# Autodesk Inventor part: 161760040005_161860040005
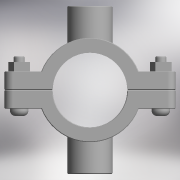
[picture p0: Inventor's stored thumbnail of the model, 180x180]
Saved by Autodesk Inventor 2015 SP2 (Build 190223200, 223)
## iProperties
Created: 2017-05
Part Number: 161760040005_161860040005
Material: Generic
Description: PLASSON DOUBLE SADDLE 40-1"/2"
Document SubType Name: Modeling
Designer: KIM
Density: 1 g/cm^3
Appearance: Default
Author: KIM
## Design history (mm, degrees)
derived "16176.ipt"
feature "Solid1::16176.ipt"
feature "Solid2::16176.ipt"
tag "TaggingFeature1"
body "Solid1"
body "Solid2"
other parameters: "d0" = 56, "d1" = 92, "d5" = 0, "d6" = 4.6, "d7" = 92, "d8" = 0.1, "d10" = 0, "d11" = 0.4, "d20" = 0.4, "d23" = 0.4, "d37" = 8, "d38" = 28, "d39" = 0, "d40" = 3, "d41" = 5, "d42" = 0, "d43" = 6, "d44" = 3, "d45" = 0, "d46" = 0.4, "d52" = 18.631, "d53" = 18, "d54" = 0, "d55" = 16, "d57" = 0, "d58" = 43.2, "d60" = 0, "d66" = 0, "d68" = 24.2203, "d69" = 18.631, "d70" = 18, "d71" = 0, "d72" = 16, "d74" = 0, "d75" = 0.4, "B_" = 16, "G_" = 18.631, "A_" = 45, "L_" = 92, "l_2" = 18
